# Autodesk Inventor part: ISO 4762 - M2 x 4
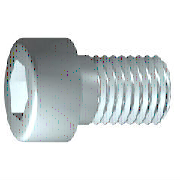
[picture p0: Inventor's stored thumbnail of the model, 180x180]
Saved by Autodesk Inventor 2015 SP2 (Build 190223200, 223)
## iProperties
IsCustomPart: 0
Created: 2012-02
Part Number: ISO 4762 - M2 x 4
Material: Edelstahl, 440C
Description: Innensechskantschraube
Document SubType Name: Modeling
Standard: ISO 4762
Designer: rYan
Standard Revision: 1998
Standards Organization: DIN
Language: de-DE
Size Designation: M2 x 4
Categories: <MemberInstance><Categories><Category DisplayName="Verbindungselemente" InternalName="e4da775c-781d-43d5-af7c-5136215cf5a6" Mnemonic="FSTN"><Category DisplayNam
Density: 7.75 g/cm^3
Mass: 0.253101 g
Surface Area: 0.751281 cm^2
Volume: 0.0326582 cm^3
Appearance: Halbpoliert
Author: rYan
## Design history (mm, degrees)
sketch "Skizze1"
  geometry: L1 (-0.5, 0)-(4, 0); L2 (4, 0)-(4, 1); L3 (4, 1)-(1, 1); L4 (1, 1)-(0.755, 1); L5 (0.755, 1)-(0, 1); L6 (0, 1)-(0, 1.9); L7 (0, 1.9)-(-2, 1.9); L8 (-2, 1.9)-(-2, 0.866); L9 (-2, 0.866)-(-1, 0.866); L10 (-1, 0.866)-(-0.5, 0); L11 (-3.2, 0)-(5.2, 0) reference; L12 (0, -0.38)-(0, 2.28) reference; L13 (1, 1)-(0, 1)
  constraints: 22 end point, 6 parallel, 2 collinear, 2 perpendicular, 1 horizontal, 1 point on line
  dimensions: "d1" = 3 distance from line of L3.end L2 (= GEL); "d2" = 0.24548 distance of L4.end L3.end (computed from GAL); "d3" = 2 distance between parallel lines of L8 L6 (= KOH); "d4" = 1 distance of L8.end L9.end (= INTI); "d5" = 60 deg angle of L10 L1; "d6" = 2 diameter of L3 L1 (= GD); "d7" = 2 diameter of L5 L1 (= BDM); "d8" = 1.73205 diameter of L9 L1 (= 1.1547 x SW); "d9" = 3.8 diameter of L7 L1 (= KOD); "d26" = 4 distance between parallel lines of L12 L2 (= NLG)
revolve "Körper" sketch "Skizze1" stored, may be unused: angle "d10" = 90 deg
sketch "Skizze2"
  geometry: L1 (0, -2.66)-(0, 2.66) reference; L2 (-2.66, 0)-(2.66, 0) reference; L3 (0.866, 0)-(0.433, -0.75); L4 (0.433, -0.75)-(-0.433, -0.75); L5 (-0.433, -0.75)-(-0.866, 0); L6 (-0.866, 0)-(-0.433, 0.75); L7 (-0.433, 0.75)-(0.433, 0.75); L8 (0.433, 0.75)-(0.866, 0); 2 further points
  constraints: 12 end point, 1 coincident, 1 horizontal alignment, 1 point on line, 12 other
extrude "Loch" join sketch "Skizze2" stored distance "d11" = 10; taper "d12" = 0 deg
workplane "Work Plane1"
fillet "Fillet2" dims "d30" = 0.1 (= R)
body "Solid1"
fillet "Rundung1" dims "d17" = 0.2 (= RR)
feature "Gewinde" dims "d13" = 3 (= GEL), "d14" = 0
chamfer "Fase1" distance "d15" = 0.24538 (= -0.5 x SPD + 0.5 x GD); stored, may be unused: second distance "d16" = 0.24538 (= GUL), angle "d27" = 45 deg
other parameters: "GD" = 2 [user parameter; used in 2 equation terms], "NLG" = 4 [user parameter; used in 1 equation term], "GEL" = 3 [user parameter; used in 2 equation terms], "KOD" = 3.8 [user parameter; used in 1 equation term], "KOH" = 2 [user parameter; used in 1 equation term], "INTI" = 1 [user parameter; used in 1 equation term], "GAL" = 0.24538 (= 0.61345 x PTC) [user parameter; used in 1 equation term], "GUL" = 0.24538 (= 0.61345 x PTC) [user parameter; used in 1 equation term], "BDM" = 2 (= NND) [user parameter; used in 1 equation term], "SW" = 1.5 [user parameter; used in 2 equation terms], "RR" = 0.2 [user parameter; used in 1 equation term], "SPD" = 1.50924 (= NND - 1.2269 x PTC) [user parameter; used in 1 equation term], "d19" = 0, "d28" = 0, "d29" = 0, "R" = 0.1 [user parameter; used in 1 equation term], "TOA" = 30 deg [user parameter], "GD1" = 1.50924 (= THREADDIA - 1.2269 x PTC) [user parameter], "THREADDIA" = 2 [user parameter; used in 1 equation term], "FAWI" = 45 deg [user parameter], "TPU" = 25 (computed from PTC) [user parameter], "PTC" = 0.4 [user parameter; used in 5 equation terms], "NND" = 2 [user parameter; used in 2 equation terms], "E0" = 1.7325 (= 1.155 x SW) [user parameter]
